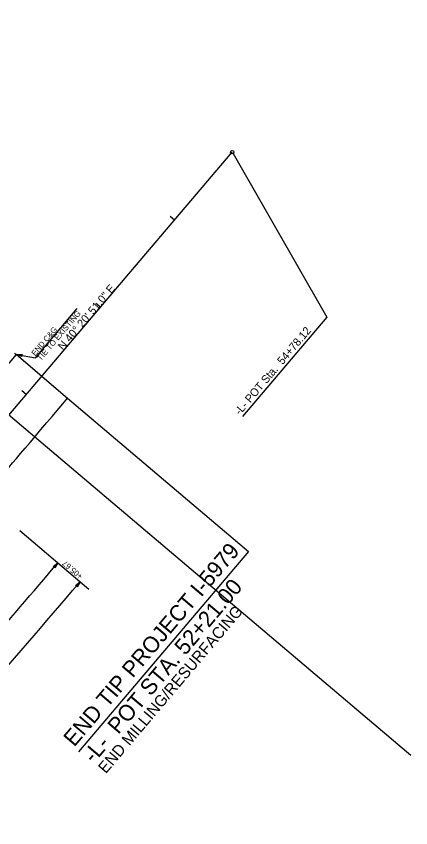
# Model space of a CAD drawing. Extents: x 1761082 to 1764358, y 421907 to 425434.
# Drawn here: x 1764013 to 1764358, y 424724 to 425434 of the extents above; entities that cross this region are included whole.
import ezdxf

# ---------------------------------------------------------------- set-up
doc = ezdxf.new("R2010")
doc.units = 0
for name, color, linetype in [('MARK HOOKS CENTER LEFT TURN ARROW CELL', 7, 'Continuous'), ('MARK HOOKS CENTER STRAIGHT LEFT TURN ARROW CELL', 7, 'Continuous'), ('MARK LEFT TURN ARROW CELL', 7, 'Continuous'), ('MARK STRAIGHT RIGHT ARROW CELL', 7, 'Continuous'), ('MARK UTURN ARROW CELL', 7, 'Continuous'), ('Prop Mkg 3ft Min Skp 3ft Wide White', 7, 'Continuous'), ('Prop Mkg Skp Wht', 7, 'Continuous'), ('Prop Mkg Solid White Multiple Diagonals V8i', 7, 'Continuous'), ('Prop Mkg Solid Yel Skip LT', 7, 'Continuous'), ('Prop Mkg Solid Yel Skip RT', 7, 'Continuous'), ('Prop Mkg Solid Yellow Lane Line', 7, 'Continuous')]:
    doc.layers.add(name, color=color, linetype=linetype)

msp = doc.modelspace()

# ---------------------------------------------------------------- linework, layer by layer
at = {"layer": 'MARK HOOKS CENTER STRAIGHT LEFT TURN ARROW CELL'}
for p, q in [((1764151.66, 425255.77), (1764147.85, 425259.01)), ((1764086.92, 425179.56), (1764083.11, 425182.8)), ((1764022.18, 425103.35), (1764018.37, 425106.59))]:
    msp.add_line(p, q, dxfattribs=at)
at = {"layer": 'MARK LEFT TURN ARROW CELL'}
msp.add_line((1764012.01, 425139.54), (1764013.54, 425138.24), dxfattribs=at)
at = {"layer": 'MARK STRAIGHT RIGHT ARROW CELL'}
msp.add_line((1763954.51, 425023.69), (1764202.24, 425315.31), dxfattribs=at)
at = {"layer": 'MARK UTURN ARROW CELL'}
for points in [[(1764202.98, 425314.01), (1764284.92, 425170.98), (1764211.23, 425083.99)], [(1764058.31, 425100.2), (1764216.36, 424965.95), (1764067.95, 424790.76)]]:
    msp.add_lwpolyline(points, dxfattribs=at)
msp.add_circle((1764202.24, 425315.31), 1.5, dxfattribs=at)
at = {"layer": 'Prop Mkg 3ft Min Skp 3ft Wide White'}
msp.add_line((1763954.51, 425023.69), (1764202.24, 425315.31), dxfattribs=at)
at = {"layer": 'Prop Mkg Skp Wht'}
msp.add_line((1764013.54, 425138.24), (1764058.31, 425100.2), dxfattribs=at)
for points in [[(1763999.96, 425122.22), (1764000.45, 425122.79), (1764003.83, 425126.74), (1764007.75, 425131.36), (1764011.94, 425136.35), (1764013.54, 425138.24)], [(1764044.77, 425084.15), (1764050.86, 425091.36), (1764055.65, 425097.04), (1764058.31, 425100.2)], [(1763983.71, 425012.25), (1763986.59, 425015.62), (1763991.65, 425021.56), (1763995.98, 425026.65), (1763999.85, 425031.2), (1764003.51, 425035.51), (1764006.98, 425039.58), (1764010.24, 425043.41), (1764013.57, 425047.33), (1764017.23, 425051.64), (1764021.23, 425056.34), (1764025.55, 425061.45), (1764030.17, 425066.9), (1764035.05, 425072.67), (1764040.19, 425078.74), (1764044.77, 425084.15)]]:
    msp.add_lwpolyline(points, dxfattribs=at)
at = {"layer": 'Prop Mkg Solid White Multiple Diagonals V8i'}
msp.add_line((1763595.27, 425434.16), (1764358.27, 424787.77), dxfattribs=at)
at = {"layer": 'Prop Mkg Solid Yel Skip RT'}
for p, q in [((1764016.61, 424984.3), (1764076.97, 424933.03)), ((1764062.64, 424931.83), (1764069.24, 424939.59))]:
    msp.add_line(p, q, dxfattribs=at)
msp.add_lwpolyline([(1764013.54, 425138.24), (1764030.28, 425135.51), (1764066.61, 425178.39)], dxfattribs=at)
for centre, radius, start, end in [((1758176.09, 429920.01), 7690.24, 318.286985, 319.798859), ((1758132.25, 429969.63), 7781.32, 317.617012, 319.652488)]:
    msp.add_arc(centre, radius, start, end, dxfattribs=at)
at = {"layer": 'Prop Mkg Solid Yellow Lane Line'}
for points in [[(1764018.43, 425136.55), (1764013.54, 425138.24), (1764018.75, 425138.31), (1764017.96, 425137.52)], [(1764045.76, 424952.89), (1764049.77, 424956.17), (1764047.09, 424951.7), (1764046.84, 424952.79)], [(1764065.23, 424936.31), (1764069.24, 424939.59), (1764066.56, 424935.12), (1764066.3, 424936.21)]]:
    msp.add_lwpolyline(points, close=True, dxfattribs=at)

# ---------------------------------------------------------------- texts
at = {"layer": 'MARK HOOKS CENTER LEFT TURN ARROW CELL'}
msp.add_text('N 40%%d 20\' 51.0" E', height=7, rotation=49.65249, dxfattribs=at).set_placement((1764054.35, 425141.53))
at = {"layer": 'MARK UTURN ARROW CELL'}
msp.add_text('-L- POT Sta.  54+78.12', height=7, rotation=49.7301, dxfattribs=at).set_placement((1764208.89, 425084.81))
at = {"layer": 'Prop Mkg Solid Yel Skip LT'}
for s, height, rotation, p in [('TIE TO EXISTING', 5, 49.7301, (1764034.95, 425132.37)), ('END C&G', 5, 49.7301, (1764029.95, 425136.61)), ('END TIP PROJECT I-5979', 14, 49.7301, (1764064.14, 424794.46)), ('+05.67', 5, 139.65249, (1764072.01, 424945.16)), ('-L-  POT STA. 52+21.00', 14, 49.7301, (1764081.13, 424780.06)), ('END MILLING/RESURFACING', 10, 49.7301, (1764091.7, 424771.11))]:
    msp.add_text(s, height=height, rotation=rotation, dxfattribs=at).set_placement(p)

doc.saveas('drawing.dxf')
